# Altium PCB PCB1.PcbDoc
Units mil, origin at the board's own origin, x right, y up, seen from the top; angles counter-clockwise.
Board outline 6000 x 4000 mil, 2 copper layers (Top Layer, Bottom Layer); 16 components, 19 nets, 79 pads, 0 vias.
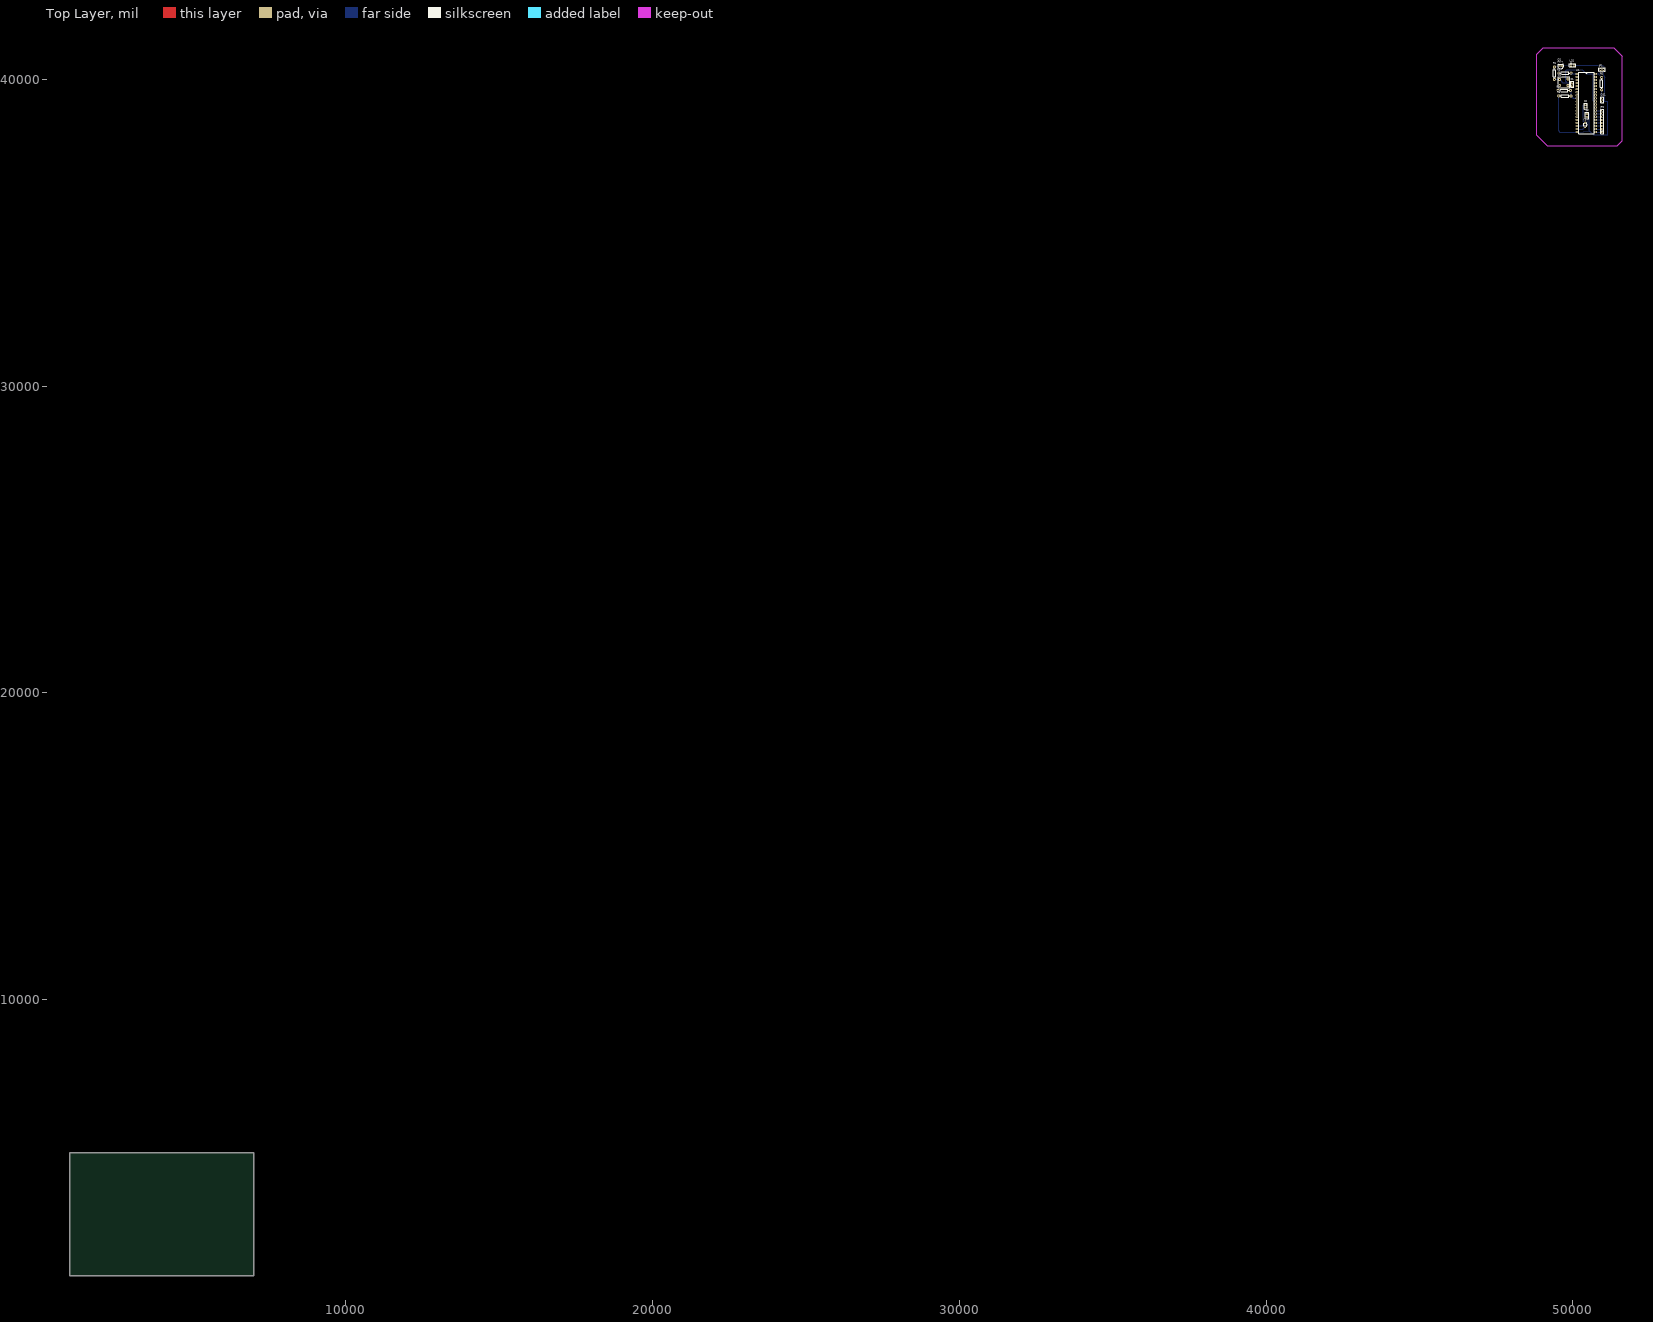
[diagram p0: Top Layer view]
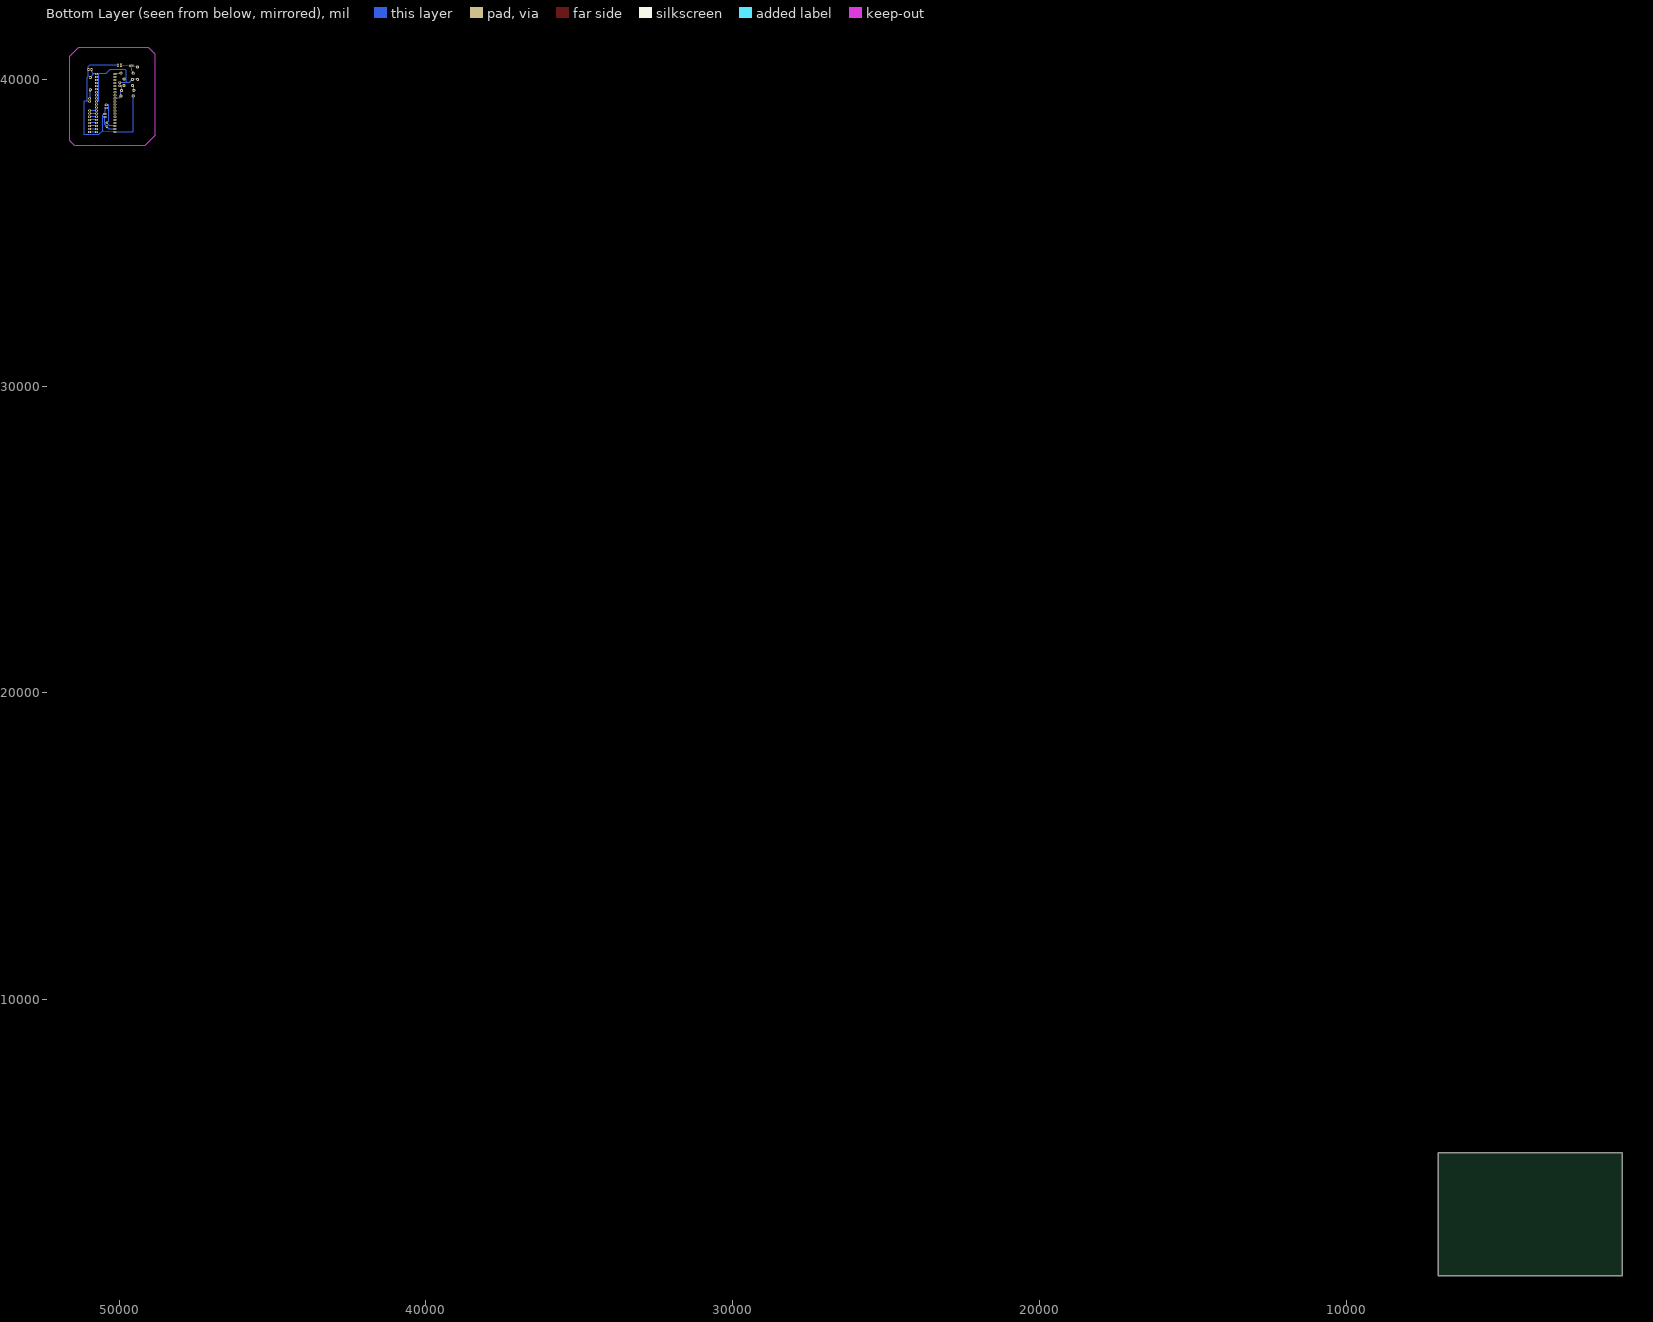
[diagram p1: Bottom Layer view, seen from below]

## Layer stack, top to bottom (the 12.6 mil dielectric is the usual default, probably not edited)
Top Layer: signal copper 1.4
Dielectric: dielectric 12.6, FR-4, Dk 4.8
Bottom Layer: signal copper 1.4

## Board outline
1000,1000 7000,1000 7000,5000 1000,5000

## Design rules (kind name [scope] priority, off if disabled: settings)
Clearance [All] p1: gap=10
ComponentClearance [All] p1: gap=10 collisioncheckmode=0
PolygonConnect [All] p1: connectstyle=Relief reliefconductorwidth=10 reliefentries=4 polygonreliefangle="90 Angle"
RoutingLayers [All] p1: top layer="Not Used" bottom layer=Any
RoutingVias [All] p1: holewidth=28 width=50 viastyle="Through Hole" minholewidth=28 minwidth=50 maxholewidth=28 maxwidth=50
SolderMaskExpansion [All] p1: expansion=4
TestPointUsage [All] p1: valid=0 allowmultiple=FALSE
Testpoint [All] p1: side=15 testpointundercomponent=TRUE minsize=40 maxsize=100 preferedsize=60 minholesize=0 maxholesize=40 preferedholesize=32 testpointgrid=1 style=1023 order=-539222988
Width [All] p1: maxlimit=50 minlimit=10 preferedwidth=10 toplayer_maxwidth=10 bottomlayer_prefwidth=40 minimp=50.000000 maximp=50.000000 favimp=50.000000
16 further rules are at their usual default settings.

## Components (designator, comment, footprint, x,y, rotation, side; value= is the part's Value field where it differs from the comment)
C1 "Cap" RAD-0.1 49980,39840 r270 top
C2 "Cap" RAD-0.1 50420,39120 r90 top
C3 "Cap" RAD-0.1 50460,38820 r270 top
DS1 "LED0" RAD0.1 50960,39380 r270 top
JP1 "Header 2" HDR1X2 51000,40320 r180 top
JP2 "Header 8H" SIP8 50960,38280 r90 top
LS1 "Speaker" PIN2 49940,40460 r0 top
Q1 "2N3904" BCY-W3/E4 49600,40440 r90 top
R1 "Res2" AXIAL-0.4 49400,40200 r270 top
R2 "Res2" AXIAL-0.4 49740,40200 r0 top
R3 "Res2" AXIAL-0.4 49740,39460 r180 top
R4 "Res2" AXIAL-0.4 49720,39640 r180 top
R5 "Res2" AXIAL-0.4 50940,39860 r270 top
S1 "SW-PB" SW0.2 49880,40080 r270 top
U1 "89S51" DIP40 50140,40180 r0 top
Y1 "XTAL" BCY-W2/D3.1 50400,38520 r0 top

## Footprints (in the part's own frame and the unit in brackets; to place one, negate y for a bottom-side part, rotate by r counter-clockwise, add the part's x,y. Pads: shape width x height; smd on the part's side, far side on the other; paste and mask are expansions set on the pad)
AXIAL-0.4 [mm]
  round 2.54 hole 0.85: 1(-5.08,0) 2(5.08,0)
  silkscreen extent -4.06,-1.02 4.06,1.02
BCY-W2/D3.1 [mil]
  round 80 hole 27.56: 1(0,61.02) 2(0,-61.02)
  silkscreen extent -61,-47 61,46
BCY-W3/E4 [mil]
  oval 80x45 hole 35.43: 1(0,-50) 2(0,0) 3(0,50)
  silkscreen extent -98,-98 59,98
DIP40 [mil]
  rect 100x69 hole 32: 1(0,0)
  oval 100x69 hole 32: 2(0,-100) 3(0,-200) 4(0,-300) 5(0,-400) 6(0,-500) 7(0,-600) 8(0,-700) 9(0,-800) 10(0,-900) 11(0,-1000) 12(0,-1100) 13(0,-1200) 14(0,-1300) 15(0,-1400) 16(0,-1500) 17(0,-1600) 18(0,-1700) 19(0,-1800) 20(0,-1900) 21(600,-1900) 22(600,-1800) 23(600,-1700) 24(600,-1600) 25(600,-1500) 26(600,-1400) 27(600,-1300) 28(600,-1200) 29(600,-1100) 30(600,-1000) 31(600,-900) 32(600,-800) 33(600,-700) 34(600,-600) 35(600,-500) 36(600,-400) 37(600,-300) 38(600,-200) 39(600,-100) 40(600,0)
  silkscreen extent 50,-1950 550,50
HDR1X2 [mil] "Connector; Header; 2 Position"
  rect 69x100 hole 35.43: 1(0,0)
  oval 69x100 hole 35.43: 2(100,0)
  silkscreen extent -50,-50 150,50
PIN2 [mil]
  rect 69x100 hole 35.43: 1(0,0)
  oval 69x100 hole 35.43: 2(100,0)
  silkscreen extent -55,-55 155,86
RAD0.1 [mil]
  oval 69x100 hole 28: 1(0,0) 2(100,0)
  silkscreen extent -50,-50 150,50
RAD-0.1 [mil]
  oval 69x100 hole 27.56: 1(-50,0) 2(50,0)
  silkscreen extent -100,-50 100,50
SIP8 [mil]
  rect 69x100 hole 32: 1(0,0)
  oval 69x100 hole 32: 2(100,0) 3(200,0) 4(300,0) 5(400,0) 6(500,0) 7(600,0) 8(700,0)
  silkscreen extent -50,-50 750,50
SW0.2 [mm]
  round 2.54 hole 0.762: 1(2.1,-8) 2(7.2,-8) 3(1.9,-1) 4(7.1,-1)
  silkscreen extent 0,-9.2 9.1,0.4

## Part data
C1 C2 C3: "Capacitor"
DS1: "Typical INFRARED GaAs LED"
JP1: "Header, 2-Pin"
JP2: "Header, 8-Pin, Right Angle"
LS1: "Loudspeaker"
Q1: "NPN General Purpose Amplifier"
R1 R2 R3 R4 R5: "Resistor"
S1: "Switch"
Y1: "Crystal Oscillator"

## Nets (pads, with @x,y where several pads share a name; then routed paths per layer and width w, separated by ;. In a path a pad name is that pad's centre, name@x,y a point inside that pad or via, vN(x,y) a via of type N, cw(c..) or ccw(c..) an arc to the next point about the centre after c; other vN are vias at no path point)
GND: C2.1 C3.1 DS1.2 JP1.1 LS1.2 R3.2 U1.20 | length 7003.6
  Bottom Layer w40: R3.2 49540,38320 49580,38280 U1.20 50540,38315 ; LS1.2 50960,40460 51000,40420 JP1.1 51000,40113 51040,40073 51040,39300 51020,39280 51145,39280 51130,38195 50675,38200 50540,38320 50540,38850 50520,38870 C3.1 50460,39070 C2.1
NetC1_2: C1.2 R3.1 R4.1 U1.9 | length 631.4
  Bottom Layer w40: C1.2 49920,39790 R4.1 49940,39620 R3.1 50020,39380 U1.9
NetC2_2: C2.2 U1.18 Y1.1 | length 984
  Bottom Layer w40: U1.18 50298.98,38480 Y1.1 50340,38641.02 50340,39150 50360,39170 C2.2
NetC3_2: C3.2 U1.19 Y1.2 | length 642.7
  Bottom Layer w40: U1.19 50321.02,38380 Y1.2 50470,38528.98 50470,38770 C3.2
NetDS1_1: DS1.1 R5.2 | length 300
  Bottom Layer w40: R5.2 50940,39380 DS1.1
NetJP2_1: JP2.1 U1.21 | length 220
  Bottom Layer w30: U1.21 JP2.1
NetJP2_2: JP2.2 U1.22 | length 220
  Bottom Layer w30: U1.22 JP2.2
NetJP2_3: JP2.3 U1.23 | length 220
  Bottom Layer w30: U1.23 JP2.3
NetJP2_4: JP2.4 U1.24 | length 220
  Bottom Layer w30: U1.24 JP2.4
NetJP2_5: JP2.5 U1.25 | length 215
  Bottom Layer w30: U1.25@50735,38690 JP2.5@50950,38690
NetJP2_6: JP2.6 U1.26 | length 220
  Bottom Layer w30: U1.26 JP2.6
NetJP2_7: JP2.7 U1.27 | length 220
  Bottom Layer w30: U1.27 JP2.7
NetJP2_8: JP2.8 U1.28 | length 220
  Bottom Layer w30: U1.28 JP2.8
NetLS1_1: LS1.1 Q1.1 | length 290.7
  Bottom Layer w30: Q1.1 LS1.1
NetQ1_2: Q1.2 R2.1 | length 250.4
  Bottom Layer w30: R2.1 49590,40320 Q1.2
NetQ1_3: Q1.3 R1.1 | length 155.2
  Bottom Layer w30: R1.1 Q1.3
NetR2_2: R2.2 U1.1 | length 220
  Bottom Layer w40: R2.2 49940,40180 U1.1
NetR4_2: R4.2 S1.2 | length 175.2
  Bottom Layer w40: R4.2 49520,39751.5 S1.2
VCC: C1.1 JP1.2 R1.2 R5.1 S1.1 U1.31 U1.40 | length 3487.9
  Bottom Layer w40: R1.2 49562.36,40000 S1.1 49672.36,39890 49800,39890 ; C1.1 49800,39890 ; U1.31 50680,39280 50660,39300 50660,40160 50680,40180 ; JP1.2 50900,40240 50840,40180 50820,40180 ; R5.1 50820,40180 ; 49800,39890 49760,39930 49760,40273 49800,40313 50307,40313 50440,40180 50680,40180 ; 50680,40180 U1.40 50820,40180
pads on no net: S1.3 S1.4 U1.2 U1.3 U1.4 U1.5 U1.6 U1.7 U1.8 U1.10 U1.11 U1.12 U1.13 U1.14 U1.15 U1.16 U1.17 U1.29 U1.30 U1.32 U1.33 U1.34 U1.35 U1.36 U1.37 U1.38 U1.39

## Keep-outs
Keep-Out Layer:
  lines w10: 48825,38170 48825,40810 49040,41025 51330,41025 51605,40750 51605,37990 51450,37835 49160,37835 48825,38170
